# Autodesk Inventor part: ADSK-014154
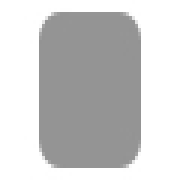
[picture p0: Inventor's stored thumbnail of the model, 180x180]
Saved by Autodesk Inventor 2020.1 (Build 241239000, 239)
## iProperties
Created: 2019-01
Part Number: ADSK-014154
Material: Stahl, weich
Document SubType Name: Modeling
Designer: lutzd
Language: de-DE
Size Designation: 5 x 36,624435 x 36,624435
Categories: <MemberInstance><Categories><Category DisplayName="Sonstige Bauteile" InternalName="5aa15e00-363f-49f2-933f-16f664388e3f" Mnemonic="OTHER"><Category DisplayName
Mass: 51.8056 g
Surface Area: 33.2935 cm^2
Volume: 6.59945 cm^3
Density: 7.85 g/cm^3
Appearance: Halbpoliert
IsCustomPart: 1
Title: end cap
Author: lutzd
Revision Number: -
Dimensions: 36,6x36,6x5 mm
Mass: 0,052 kg
DocNumber: ADSK-014154
Folder: 01 - Themengebiete\Simplification\01 - Packaging machine\
VDS_Category: 3D Komponenten
VDS_NumSchm: Autodesk
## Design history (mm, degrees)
sketch "Sketch1"
  geometry: L1 (0, 20.175)-(0, -21.446); L2 (-20.203, 0)-(20.169, 0); L3 (-18.312, 18.312)-(18.312, 18.312); L4 (18.312, 18.312)-(18.312, -18.312); L5 (18.312, -18.312)-(-18.312, -18.312); L6 (-18.312, -18.312)-(-18.312, 18.312); 1 further point
  constraints: 12 end point, 2 horizontal, 2 parallel, 2 point on line, 1 perpendicular, 1 vertical
  dimensions: "d0" = 36.62444 distance between parallel lines of L5 L3 (= height); "d1" = 18.31222 distance between parallel lines of L2 L3 (= 0.5 x height); "d2" = 36.62444 distance between parallel lines of L6 L4 (= width); "d3" = 18.31222 distance between parallel lines of L6 L1 (= 0.5 x width)
extrude "Extrusion1" new body sketch "Sketch1" distance "d4" = 5 (= thickness); taper "d5" = 0 deg
fillet "Fillet1" dims "d6" = 5 (= fillet), "d7" = 0, "fillet" = 5 [user parameter; used in 1 equation term]
chamfer "Chamfer1" distance "d8" = 0 (computed from chamfer); stored, may be unused: second distance "d9" = 2, angle "d10" = 45 deg; dims "d11" = 0, "chamfer" = 0 [user parameter; used in 1 equation term]
body "Solid1"
other parameters: "thickness" = 5 [user parameter; used in 1 equation term], "width" = 36.62444 [user parameter; used in 2 equation terms], "height" = 36.62444 [user parameter; used in 2 equation terms]
